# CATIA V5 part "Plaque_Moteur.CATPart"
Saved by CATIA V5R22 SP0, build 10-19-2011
Part number: Plaque_Moteur
Material "Acier": density 7860 kg/m3, Young's modulus 2e+11 Pa, Poisson ratio 0.266, thermal expansion 1.17e-05 1/K
Bounding box of the stored display mesh (mm): x -20 to 20, y -41 to 41, z 0 to 3
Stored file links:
  U:\S9A\PER\CAO\Assemblage\Cadre\Chariot_X\Plaque_Moteur.CATPart
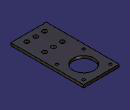
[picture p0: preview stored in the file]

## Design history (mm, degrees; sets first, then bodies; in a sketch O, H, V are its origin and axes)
Body1 (main body), material "Acier"
  Sketch1 on xy-plane, origin (0, 0, 0), H (1, 0, 0), V (0, 1, 0)
    line L1 (20, 41) -> (20, -41)
    line L2 (20, -41) -> (-20, -41)
    line L3 (-20, -41) -> (-20, 41)
    line L4 (-20, 41) -> (20, 41)
    length L4 = 40
    length L1 = 82
    vertical: L1 V, L3 V
    horizontal: L2 H, L4 H
    equidistance: L1 L3 O, L2 L4 O
  Pad1: profile Sketch1, direction (0, 0, 1), length 3
  Sketch2 on end face of Pad1, origin (11.0599, -37.2607, 3), H (1, 0, 0), V (0, 1, 0)
    point P1 (-1.0599, 4.2607)
    reference projected line E1 (8.9401, -3.7393) -> (8.9401, 78.2607) from edge [face of Pad1 from Sketch1.L1 | end face of Pad1]
    reference projected line E2 (-31.0599, -3.7393) -> (8.9401, -3.7393) from edge [face of Pad1 from Sketch1.L2 | end face of Pad1]
    distance P1 E1 = 10
    distance P1 E2 = 8
  Hole1: placed by Sketch2, at (10, -33, 3) direction (0, 0, -1), diameter 5, depth 10
  RectPattern1: of Hole1, direction 1 instances 3, spacing 10, along end face of Pad1 reversed, direction 2 instances 2, spacing 20, along end face of Pad1
  Sketch3 on end face of Pad1, origin (14.3228, 17.7262, 3), H (1, 0, 0), V (0, 1, 0)
    point P1 (0.6772, 18.2738)
    reference projected line E1 (5.6772, -58.7262) -> (5.6772, 23.2738) from edge [face of Pad1 from Sketch1.L1 | end face of Pad1]
    reference projected line E2 (5.6772, 23.2738) -> (-34.3228, 23.2738) from edge [face of Pad1 from Sketch1.L4 | end face of Pad1]
    distance P1 E1 = 5
    distance P1 E2 = 5
  Hole2: placed by Sketch3, at (15, 36, 3) direction (0, 0, -1), diameter 3, depth 10
  RectPattern2: of Hole2, direction 1 instances 2, spacing 30, along end face of Pad1 reversed, direction 2 instances 2, spacing 30, along end face of Pad1 reversed
  Sketch4 on end face of Pad1, origin (1.2067, 25.9537, 3), H (1, 0, 0), V (0, 1, 0)
    point P1 (-1.2067, -4.9537)
    reference projected line E1 (18.7933, -66.9537) -> (18.7933, 15.0463) from edge [face of Pad1 from Sketch1.L1 | end face of Pad1]
    reference projected line E2 (18.7933, 15.0463) -> (-21.2067, 15.0463) from edge [face of Pad1 from Sketch1.L4 | end face of Pad1]
    distance P1 E1 = 20
    distance P1 E2 = 20
  Hole3: placed by Sketch4, at (0, 21, 3) direction (0, 0, -1), diameter 24, through (limit type 6)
